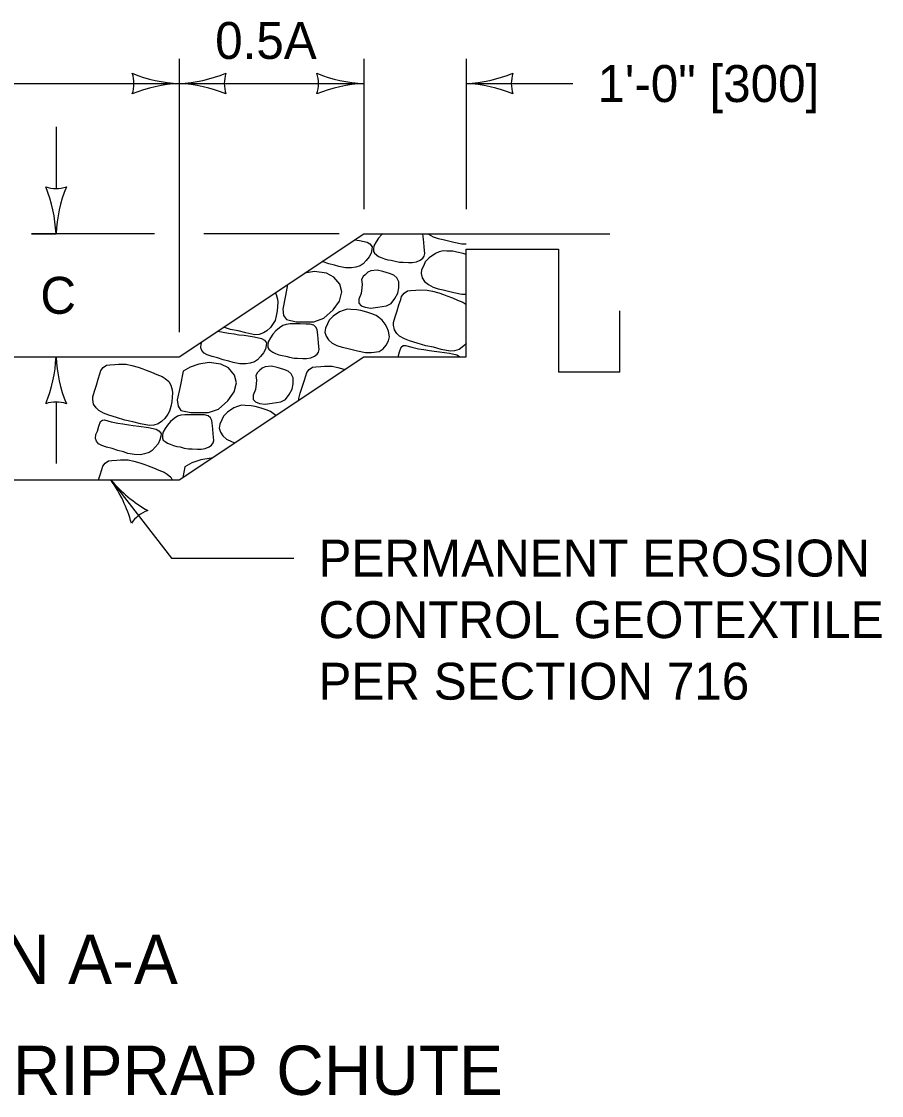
# Model space of a CAD drawing. Extents: x 49991.4 to 50021, y 49987.6 to 50011.4.
# Drawn here: x 50005.605 to 50007.003, y 49994.565 to 49996.31 of the extents above; entities that cross this region are included whole.
import ezdxf

# ---------------------------------------------------------------- set-up
doc = ezdxf.new("R2010")
doc.units = 0
for name, color, linetype in [('Level 1', 7, 'Continuous'), ('Level 2', 7, 'Continuous'), ('Level 3', 7, 'Continuous')]:
    doc.layers.add(name, color=color, linetype=linetype)

msp = doc.modelspace()

# ---------------------------------------------------------------- linework, layer by layer
at = {"layer": 'Level 1'}
for p, q in [((50005.8616, 49995.7648), (50006.1616, 49995.9648)), ((50006.1616, 49995.9648), (50006.5616, 49995.9648)), ((50006.478, 49995.9398), (50006.478, 49995.7398)), ((50006.578, 49995.7398), (50006.578, 49995.8398)), ((50005.2616, 49995.7648), (50005.8616, 49995.7648)), ((50005.8616, 49995.5648), (50006.1616, 49995.7648)), ((50006.1616, 49995.7648), (50006.328, 49995.7648)), ((50006.578, 49995.7398), (50006.478, 49995.7398)), ((50005.2616, 49995.5648), (50005.8616, 49995.5648))]:
    msp.add_line(p, q, dxfattribs=at)
for points in [[(50006.1465, 49995.9547), (50006.155, 49995.9536), (50006.1673, 49995.9509), (50006.1717, 49995.9482), (50006.1752, 49995.9437), (50006.1747, 49995.9392), (50006.1735, 49995.9332), (50006.1703, 49995.9271), (50006.1658, 49995.9213), (50006.1609, 49995.9159), (50006.156, 49995.9128), (50006.1486, 49995.9106), (50006.1417, 49995.9092), (50006.1318, 49995.9094), (50006.1213, 49995.9115), (50006.1141, 49995.9137), (50006.105, 49995.9159), (50006.0959, 49995.9191), (50006.0938, 49995.9196)], [(50006.1928, 49995.9648), (50006.1907, 49995.963), (50006.1858, 49995.9575), (50006.1818, 49995.9519), (50006.1781, 49995.9451), (50006.1774, 49995.9398), (50006.1774, 49995.936), (50006.1789, 49995.933), (50006.1821, 49995.9306), (50006.1855, 49995.9281), (50006.1902, 49995.9263), (50006.1956, 49995.9241), (50006.201, 49995.9227), (50006.2064, 49995.9219), (50006.2128, 49995.9201), (50006.22, 49995.9187), (50006.2259, 49995.9187), (50006.2343, 49995.9183), (50006.2404, 49995.9183), (50006.2471, 49995.9192), (50006.2535, 49995.9219), (50006.2574, 49995.925), (50006.2596, 49995.9286), (50006.2608, 49995.9326), (50006.2599, 49995.9431), (50006.2591, 49995.9505), (50006.2586, 49995.9559), (50006.2577, 49995.9648)], [(50006.2656, 49995.9648), (50006.2667, 49995.9639), (50006.2744, 49995.9598), (50006.2825, 49995.9571), (50006.2906, 49995.9554), (50006.3079, 49995.9511), (50006.3209, 49995.9486), (50006.328, 49995.9485)], [(50006.328, 49995.9309), (50006.3231, 49995.9325), (50006.313, 49995.935), (50006.3064, 49995.9363), (50006.2968, 49995.9365), (50006.2909, 49995.937), (50006.2842, 49995.9352), (50006.2783, 49995.9327), (50006.268, 49995.9258), (50006.2616, 49995.9193), (50006.2591, 49995.9132), (50006.2557, 49995.9063), (50006.2547, 49995.9), (50006.2566, 49995.8933), (50006.2606, 49995.8873), (50006.2667, 49995.8821), (50006.2744, 49995.8781), (50006.2825, 49995.8754), (50006.2906, 49995.8736), (50006.3079, 49995.8694), (50006.3209, 49995.8669), (50006.328, 49995.8667)], [(50006.328, 49995.7648), (50006.328, 49995.9398), (50006.478, 49995.9398)], [(50006.038, 49995.8824), (50006.0344, 49995.8643), (50006.0299, 49995.8424), (50006.0314, 49995.8321), (50006.0359, 49995.8254), (50006.0516, 49995.8218), (50006.0807, 49995.8218), (50006.0969, 49995.8276), (50006.1122, 49995.8411), (50006.122, 49995.8554), (50006.126, 49995.8702), (50006.123, 49995.8827), (50006.1132, 49995.8943), (50006.1009, 49995.9006), (50006.0817, 49995.9033), (50006.0654, 49995.9007)], [(50006.0179, 49995.869), (50006.0195, 49995.8661), (50006.0215, 49995.8587), (50006.0219, 49995.8538), (50006.0217, 49995.8466), (50006.0212, 49995.8395), (50006.0192, 49995.8316), (50006.0175, 49995.824), (50006.0146, 49995.8191), (50006.0099, 49995.8124), (50006.0042, 49995.8072), (50005.999, 49995.8036), (50005.9917, 49995.8014), (50005.9845, 49995.8007), (50005.97, 49995.8036), (50005.9574, 49995.807), (50005.9449, 49995.8095), (50005.9337, 49995.8129)], [(50006.328, 49995.7867), (50006.3273, 49995.7857), (50006.3217, 49995.7805), (50006.3165, 49995.7769), (50006.3091, 49995.7747), (50006.302, 49995.774), (50006.2874, 49995.7769), (50006.2749, 49995.7803), (50006.2623, 49995.7828), (50006.2485, 49995.787), (50006.236, 49995.7908), (50006.2276, 49995.7942), (50006.2197, 49995.7984), (50006.2153, 49995.8027), (50006.2114, 49995.8087), (50006.2101, 49995.8161), (50006.2101, 49995.8208), (50006.2126, 49995.83), (50006.2158, 49995.8396), (50006.2187, 49995.8495), (50006.2217, 49995.8578), (50006.2232, 49995.8631), (50006.2271, 49995.8683), (50006.2325, 49995.8721), (50006.2377, 49995.8728), (50006.2461, 49995.873), (50006.252, 49995.8737), (50006.2645, 49995.8734), (50006.2736, 49995.8716), (50006.2835, 49995.869), (50006.2914, 49995.8663), (50006.2968, 49995.864), (50006.3057, 49995.8605), (50006.314, 49995.8569), (50006.3226, 49995.8537), (50006.3276, 49995.8504), (50006.328, 49995.85)], [(50005.9243, 49995.8066), (50005.9333, 49995.8048), (50005.9417, 49995.8034), (50005.9511, 49995.8021), (50005.9584, 49995.8007), (50005.9673, 49995.7998), (50005.9833, 49995.7976), (50005.9956, 49995.7949), (50006.0001, 49995.7922), (50006.0035, 49995.7878), (50006.003, 49995.7833), (50006.0018, 49995.7772), (50005.9986, 49995.7712), (50005.9941, 49995.7654), (50005.9892, 49995.76), (50005.9843, 49995.7569), (50005.9769, 49995.7546), (50005.97, 49995.7533), (50005.9602, 49995.7535), (50005.9496, 49995.7555), (50005.9424, 49995.7578), (50005.9333, 49995.76), (50005.9242, 49995.7631), (50005.9151, 49995.7654), (50005.9072, 49995.7681), (50005.9021, 49995.771), (50005.8986, 49995.7752), (50005.8969, 49995.7797), (50005.8974, 49995.786), (50005.8992, 49995.7899)], [(50006.2174, 49995.7648), (50006.2175, 49995.7651), (50006.22, 49995.7729), (50006.2227, 49995.7805), (50006.2257, 49995.783), (50006.2294, 49995.7834), (50006.2399, 49995.7803), (50006.2508, 49995.7781), (50006.2591, 49995.7767), (50006.2685, 49995.7754), (50006.2759, 49995.774), (50006.2847, 49995.7731), (50006.3008, 49995.7709), (50006.3131, 49995.7682), (50006.3175, 49995.7655), (50006.318, 49995.7648)], [(50005.8253, 49995.7361), (50005.8339, 49995.733), (50005.8389, 49995.7296), (50005.8448, 49995.7249), (50005.8482, 49995.7186), (50005.8502, 49995.7113), (50005.8507, 49995.7063), (50005.8504, 49995.6992), (50005.8499, 49995.692), (50005.848, 49995.6842), (50005.8462, 49995.6765), (50005.8433, 49995.6716), (50005.8386, 49995.6649), (50005.833, 49995.6598), (50005.8278, 49995.6562), (50005.8204, 49995.6539), (50005.8133, 49995.6533), (50005.7987, 49995.6562), (50005.7862, 49995.6595), (50005.7736, 49995.662), (50005.7598, 49995.6663), (50005.7473, 49995.6701), (50005.7389, 49995.6734), (50005.731, 49995.6777), (50005.7266, 49995.6819), (50005.7226, 49995.688), (50005.7214, 49995.6954), (50005.7214, 49995.7001), (50005.7239, 49995.7092), (50005.7271, 49995.7189), (50005.73, 49995.7287), (50005.733, 49995.737), (50005.7345, 49995.7424), (50005.7384, 49995.7475), (50005.7438, 49995.7513), (50005.749, 49995.752), (50005.7574, 49995.7522), (50005.7633, 49995.7529), (50005.7758, 49995.7527), (50005.7849, 49995.7509), (50005.7948, 49995.7482), (50005.8027, 49995.7455), (50005.8081, 49995.7433), (50005.8169, 49995.7397), (50005.8253, 49995.7361)], [(50006.056, 49995.6944), (50006.056, 49995.6969), (50006.0585, 49995.7061), (50006.0617, 49995.7157), (50006.0646, 49995.7255), (50006.0676, 49995.7338), (50006.0691, 49995.7392), (50006.073, 49995.7444), (50006.0784, 49995.7482), (50006.0836, 49995.7488), (50006.092, 49995.7491), (50006.0979, 49995.7497), (50006.1104, 49995.7495), (50006.1195, 49995.7477), (50006.1294, 49995.745), (50006.1311, 49995.7445)], [(50006.0186, 49995.6695), (50006.0142, 49995.6727), (50006.01, 49995.6761), (50006.0033, 49995.679), (50005.9952, 49995.6817), (50005.9851, 49995.6841), (50005.9785, 49995.6855), (50005.9689, 49995.6857), (50005.963, 49995.6861), (50005.9563, 49995.6844), (50005.9504, 49995.6819), (50005.9401, 49995.675), (50005.9337, 49995.6685), (50005.9312, 49995.6624), (50005.9277, 49995.6555), (50005.9268, 49995.6492), (50005.9287, 49995.6425), (50005.9327, 49995.6364), (50005.9388, 49995.6313), (50005.9465, 49995.6273), (50005.9523, 49995.6253)], [(50005.7307, 49995.5648), (50005.7332, 49995.5733), (50005.7362, 49995.5816), (50005.7376, 49995.587), (50005.7416, 49995.5921), (50005.747, 49995.5959), (50005.7522, 49995.5966), (50005.7605, 49995.5968), (50005.7664, 49995.5975), (50005.779, 49995.5973), (50005.7881, 49995.5955), (50005.798, 49995.5928), (50005.8058, 49995.5901), (50005.8113, 49995.5879), (50005.8201, 49995.5843), (50005.8285, 49995.5807)], [(50005.9148, 49995.6003), (50005.9136, 49995.6004), (50005.8968, 49995.5977), (50005.8825, 49995.5928), (50005.8711, 49995.5859), (50005.8678, 49995.5689)], [(50005.8285, 49995.5807), (50005.8371, 49995.5776), (50005.842, 49995.5742), (50005.8479, 49995.5695), (50005.8505, 49995.5648)]]:
    msp.add_lwpolyline(points, dxfattribs=at)
for points in [[(50006.173, 49995.9046), (50006.1684, 49995.9024), (50006.1642, 49995.8983), (50006.1607, 49995.8952), (50006.158, 49995.8905), (50006.159, 49995.8827), (50006.1585, 49995.8771), (50006.1575, 49995.8679), (50006.1536, 49995.8587), (50006.1538, 49995.8518), (50006.1575, 49995.8479), (50006.1639, 49995.8453), (50006.1733, 49995.8441), (50006.1846, 49995.8457), (50006.1984, 49995.8475), (50006.2063, 49995.8515), (50006.2119, 49995.8594), (50006.2171, 49995.8681), (50006.2188, 49995.8768), (50006.2186, 49995.8867), (50006.2154, 49995.893), (50006.2105, 49995.8977), (50006.2033, 49995.9001), (50006.1925, 49995.9033), (50006.1834, 49995.9057)], [(50006.1221, 49995.8378), (50006.1117, 49995.8309), (50006.1053, 49995.8244), (50006.1029, 49995.8184), (50006.0994, 49995.8114), (50006.0984, 49995.8051), (50006.1004, 49995.7984), (50006.1044, 49995.7924), (50006.1105, 49995.7872), (50006.1181, 49995.7832), (50006.1263, 49995.7805), (50006.1344, 49995.7787), (50006.1516, 49995.7745), (50006.1647, 49995.772), (50006.174, 49995.7718), (50006.1866, 49995.7733), (50006.1932, 49995.778), (50006.1982, 49995.7839), (50006.2021, 49995.791), (50006.2033, 49995.7973), (50006.2016, 49995.8065), (50006.1992, 49995.813), (50006.1962, 49995.8179), (50006.1913, 49995.8246), (50006.1859, 49995.8287), (50006.1817, 49995.832), (50006.175, 49995.8349), (50006.1669, 49995.8376), (50006.1568, 49995.8401), (50006.1502, 49995.8414), (50006.1405, 49995.8416), (50006.1346, 49995.8421), (50006.128, 49995.8403)], [(50006.0357, 49995.8176), (50006.0301, 49995.8158), (50006.0249, 49995.812), (50006.019, 49995.8071), (50006.0141, 49995.8015), (50006.0101, 49995.7959), (50006.0064, 49995.7892), (50006.0057, 49995.7838), (50006.0057, 49995.78), (50006.0072, 49995.7771), (50006.0104, 49995.7746), (50006.0138, 49995.7722), (50006.0185, 49995.7704), (50006.0239, 49995.7681), (50006.0293, 49995.7668), (50006.0348, 49995.7659), (50006.0412, 49995.7641), (50006.0483, 49995.7628), (50006.0542, 49995.7628), (50006.0626, 49995.7623), (50006.0687, 49995.7623), (50006.0754, 49995.7632), (50006.0818, 49995.7659), (50006.0857, 49995.769), (50006.0879, 49995.7726), (50006.0892, 49995.7767), (50006.0882, 49995.7872), (50006.0874, 49995.7946), (50006.0869, 49995.7999), (50006.086, 49995.8091), (50006.0837, 49995.8129), (50006.0803, 49995.8163), (50006.0744, 49995.8179), (50006.0673, 49995.8181), (50006.0581, 49995.8183), (50006.049, 49995.8183), (50006.0421, 49995.8183)], [(50005.868, 49995.7413), (50005.8631, 49995.7169), (50005.8587, 49995.6949), (50005.8602, 49995.6846), (50005.8646, 49995.6779), (50005.8804, 49995.6743), (50005.9094, 49995.6743), (50005.9257, 49995.6801), (50005.9409, 49995.6936), (50005.9508, 49995.7079), (50005.9547, 49995.7227), (50005.9518, 49995.7352), (50005.9419, 49995.7469), (50005.9296, 49995.7531), (50005.9104, 49995.7558), (50005.8936, 49995.7531), (50005.8794, 49995.7482)], [(50006.0014, 49995.7487), (50005.9967, 49995.7464), (50005.9925, 49995.7424), (50005.989, 49995.7393), (50005.9863, 49995.7346), (50005.9873, 49995.7267), (50005.9868, 49995.7211), (50005.9858, 49995.7119), (50005.9819, 49995.7028), (50005.9822, 49995.6958), (50005.9858, 49995.692), (50005.9923, 49995.6893), (50006.0016, 49995.6882), (50006.0129, 49995.6898), (50006.0267, 49995.6916), (50006.0346, 49995.6956), (50006.0403, 49995.7034), (50006.0454, 49995.7122), (50006.0472, 49995.7209), (50006.0469, 49995.7307), (50006.0437, 49995.737), (50006.0388, 49995.7417), (50006.0316, 49995.7442), (50006.0208, 49995.7473), (50006.0117, 49995.7498)], [(50005.734, 49995.6598), (50005.7369, 49995.6622), (50005.7406, 49995.6627), (50005.7512, 49995.6595), (50005.7621, 49995.6573), (50005.7704, 49995.656), (50005.7798, 49995.6546), (50005.7872, 49995.6533), (50005.796, 49995.6524), (50005.812, 49995.6501), (50005.8244, 49995.6474), (50005.8288, 49995.6448), (50005.8322, 49995.6403), (50005.8317, 49995.6358), (50005.8305, 49995.6298), (50005.8273, 49995.6237), (50005.8229, 49995.6179), (50005.818, 49995.6125), (50005.813, 49995.6094), (50005.8056, 49995.6071), (50005.7988, 49995.6058), (50005.7889, 49995.606), (50005.7783, 49995.608), (50005.7712, 49995.6103), (50005.7621, 49995.6125), (50005.753, 49995.6157), (50005.7438, 49995.6179), (50005.736, 49995.6206), (50005.7308, 49995.6235), (50005.7273, 49995.6277), (50005.7256, 49995.6322), (50005.7261, 49995.6385), (50005.7288, 49995.6443), (50005.7313, 49995.6521)], [(50005.8645, 49995.6702), (50005.8588, 49995.6684), (50005.8536, 49995.6646), (50005.8477, 49995.6596), (50005.8428, 49995.654), (50005.8389, 49995.6484), (50005.8352, 49995.6417), (50005.8344, 49995.6363), (50005.8344, 49995.6325), (50005.8359, 49995.6296), (50005.8391, 49995.6272), (50005.8426, 49995.6247), (50005.8472, 49995.6229), (50005.8527, 49995.6207), (50005.8581, 49995.6193), (50005.8635, 49995.6184), (50005.8699, 49995.6166), (50005.877, 49995.6153), (50005.8829, 49995.6153), (50005.8913, 49995.6149), (50005.8975, 49995.6149), (50005.9041, 49995.6157), (50005.9105, 49995.6184), (50005.9145, 49995.6216), (50005.9167, 49995.6252), (50005.9179, 49995.6292), (50005.9169, 49995.6397), (50005.9162, 49995.6471), (50005.9157, 49995.6525), (50005.9147, 49995.6616), (50005.9125, 49995.6655), (50005.909, 49995.6688), (50005.9031, 49995.6704), (50005.896, 49995.6706), (50005.8869, 49995.6708), (50005.8778, 49995.6708), (50005.8709, 49995.6708)]]:
    msp.add_lwpolyline(points, close=True, dxfattribs=at)
at = {"layer": 'Level 3'}
for p, q in [((50005.8616, 49996.2488), (50005.8616, 49995.8048)), ((50006.1616, 49996.2488), (50006.1616, 49996.0048)), ((50006.328, 49996.2488), (50006.328, 49996.0048)), ((50005.2616, 49996.2088), (50005.8616, 49996.2088)), ((50005.8616, 49996.2088), (50006.1616, 49996.2088)), ((50006.328, 49996.2088), (50006.5014, 49996.2088)), ((50005.6616, 49996.1383), (50005.6616, 49996.0383)), ((50005.8216, 49995.9648), (50005.6216, 49995.9648)), ((50005.6216, 49995.9648), (50005.6616, 49995.9648)), ((50006.1216, 49995.9648), (50005.9016, 49995.9648)), ((50005.6616, 49995.6914), (50005.6616, 49995.5914)), ((50005.7506, 49995.5648), (50005.8494, 49995.4379)), ((50005.8494, 49995.4379), (50006.0482, 49995.4379))]:
    msp.add_line(p, q, dxfattribs=at)
for centre, radius, start, end in [((50005.8708, 49996.4309), 0.2223, 247.456, 267.6395), ((50005.7334, 49996.2088), 0.0548, 342.1388, 17.8612), ((50005.8501, 49996.4415), 0.233, 272.8273, 292.0772), ((50005.9898, 49996.2088), 0.0548, 162.1388, 197.8612), ((50006.1708, 49996.4309), 0.2223, 247.456, 267.6395), ((50006.0334, 49996.2088), 0.0548, 342.1388, 17.8612), ((50006.3165, 49996.4415), 0.233, 272.8273, 292.0772), ((50006.4562, 49996.2088), 0.0548, 162.1388, 197.8612), ((50005.8731, 49995.9761), 0.233, 92.8273, 112.0772), ((50005.8525, 49995.9866), 0.2223, 67.456, 87.6395), ((50006.1731, 49995.9761), 0.233, 92.8273, 112.0772), ((50006.3189, 49995.9866), 0.2223, 67.456, 87.6395), ((50005.6616, 49996.093), 0.0548, 252.1388, 287.8612), ((50005.4289, 49995.9533), 0.233, 2.8273, 22.0772), ((50005.8838, 49995.9557), 0.2223, 157.456, 177.6395), ((50005.4395, 49995.774), 0.2223, 337.456, 357.6395), ((50005.8943, 49995.7763), 0.233, 182.8273, 202.0772), ((50005.6616, 49995.6366), 0.0548, 72.1388, 107.8612), ((50005.5697, 49995.4357), 0.2223, 15.3374, 35.5209), ((50005.9272, 49995.7168), 0.233, 220.7087, 239.9586), ((50005.8293, 49995.4636), 0.0548, 110.0202, 145.7426)]:
    msp.add_arc(centre, radius, start, end, dxfattribs=at)

# ---------------------------------------------------------------- texts
at = {"layer": 'Level 2'}
for s, height, p in [('0.5A', 0.06, (50005.9202, 49996.2488)), ('1\'-0" [300]', 0.06, (50006.5414, 49996.1788)), ('C', 0.06, (50005.6361, 49995.8348)), ('PERMANENT EROSION', 0.06, (50006.0881, 49995.4079)), ('CONTROL GEOTEXTILE', 0.06, (50006.0881, 49995.3079)), ('PER SECTION 716', 0.06, (50006.0881, 49995.2079)), ('SECTION A-A', 0.08, (50005.176, 49994.746)), ('RIPRAP & GROUTED RIPRAP CHUTE', 0.08, (50004.4977, 49994.5659))]:
    msp.add_text(s, height=height, dxfattribs=at).set_placement(p)

doc.saveas('drawing.dxf')
